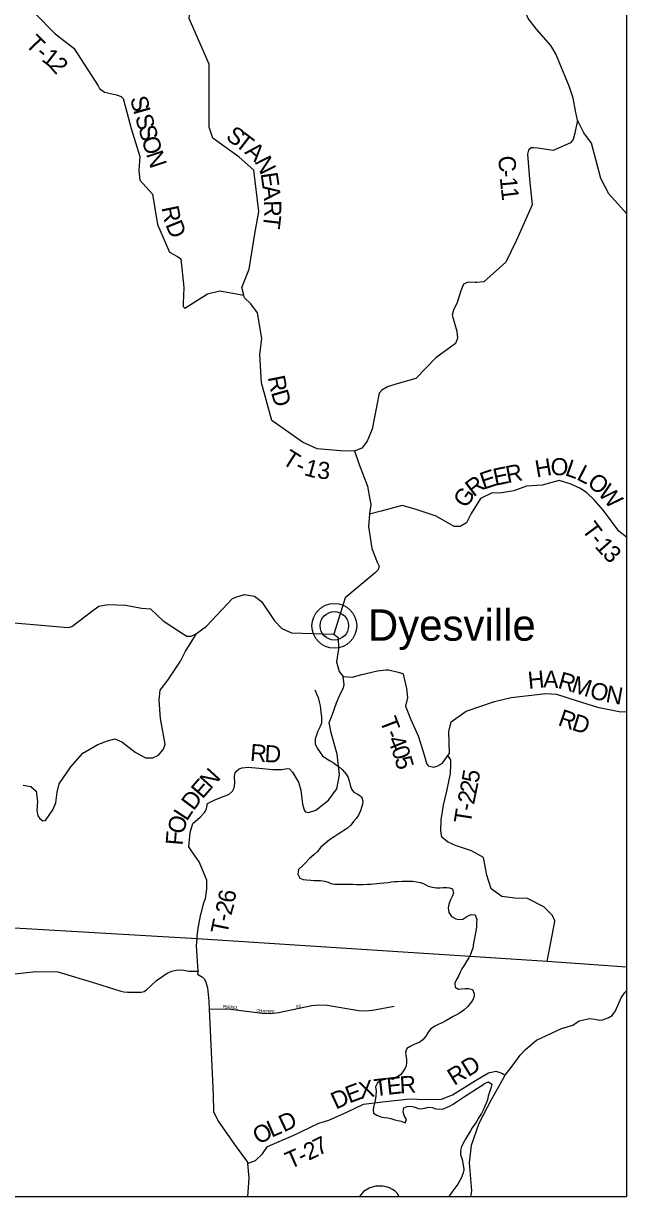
# Model space of a CAD drawing. Extents: x -15 to 405, y -40 to 87.
# Drawn here: x -10.265 to -8.262, y 14.129 to 18.029 of the extents above; entities that cross this region are included whole.
import ezdxf

# ---------------------------------------------------------------- set-up
doc = ezdxf.new("R2010")
doc.units = 0
for name, color, linetype in [('GM_P_State_Location', 7, 'Continuous'), ('GM_X_Major_Lake', 7, 'Continuous'), ('GM_X_Major_Lake_Text', 7, 'Continuous'), ('GM_X_Major_River', 7, 'Continuous'), ('GM_X_Minor_Lake', 7, 'Continuous'), ('GM_X_Minor_River', 7, 'Continuous'), ('GM_X_Rail_Line', 7, 'Continuous'), ('GM_X_Township', 7, 'Continuous'), ('GM_X_Township_Road', 7, 'Continuous'), ('GM_X_Township_ROW', 7, 'Continuous'), ('GM_X_Township_Subdivision_Text', 7, 'Continuous'), ('GM_X_Township_Text', 7, 'Continuous')]:
    doc.layers.add(name, color=color, linetype=linetype)

msp = doc.modelspace()

# ---------------------------------------------------------------- linework, layer by layer
at = {"layer": 'GM_P_State_Location'}
for points in [[(-9.1653, 16.608), (-9.1986, 16.6073), (-9.2895, 16.6146), (-9.338, 16.6373), (-9.4395, 16.7094), (-9.4747, 16.8339), (-9.4804, 16.9288), (-9.4733, 16.982), (-9.4872, 17.0673), (-9.5096, 17.0974), (-9.5307, 17.1173), (-9.5328, 17.1252), (-9.5398, 17.1513), (-9.5154, 17.2124), (-9.4962, 17.3291), (-9.4833, 17.4044), (-9.4997, 17.5413), (-9.5484, 17.5844), (-9.6358, 17.648), (-9.6476, 17.6847), (-9.6484, 17.8939), (-9.7143, 18.045), (-9.6672, 18.4388)], [(-10.228, 18.0646), (-10.1595, 17.9948), (-10.0974, 17.9473), (-10.017, 17.8221), (-10.0122, 17.8123), (-9.9955, 17.8007), (-9.9559, 17.7913), (-9.9406, 17.7857), (-9.9341, 17.7798), (-9.9265, 17.7503), (-9.9075, 17.6799), (-9.8787, 17.5864), (-9.882, 17.5397), (-9.8786, 17.5082), (-9.8367, 17.4616), (-9.82, 17.3608), (-9.7798, 17.269), (-9.7538, 17.2537), (-9.7427, 17.2466), (-9.7321, 17.1507), (-9.7346, 17.0975), (-9.7341, 17.088), (-9.7291, 17.0827), (-9.654, 17.1303), (-9.6123, 17.1406), (-9.5328, 17.1252)], [(-8.2623, 16.3215), (-8.2872, 16.3408), (-8.3101, 16.3711), (-8.3391, 16.4097), (-8.3693, 16.4448), (-8.3941, 16.4686), (-8.4153, 16.4832), (-8.4491, 16.4986), (-8.4858, 16.5099), (-8.5427, 16.4945), (-8.5943, 16.4908), (-8.6368, 16.475), (-8.6763, 16.468), (-8.7108, 16.4675), (-8.7476, 16.4495), (-8.7782, 16.3996), (-8.794, 16.3684), (-8.8141, 16.3569), (-8.8342, 16.3564), (-8.8947, 16.3914), (-8.9643, 16.4146), (-9.0069, 16.4262), (-9.0775, 16.4076), (-9.1152, 16.3978)], [(-10.2654, 15.4963), (-10.2403, 15.4918), (-10.2226, 15.4764), (-10.2184, 15.4426), (-10.2202, 15.4127), (-10.2166, 15.3941), (-10.2102, 15.3857), (-10.2004, 15.3776), (-10.1916, 15.379), (-10.1677, 15.4147), (-10.1576, 15.4381), (-10.153, 15.4733), (-10.1463, 15.5008), (-10.1073, 15.5572), (-10.0673, 15.6029), (-10.0183, 15.6319), (-9.9862, 15.644), (-9.9614, 15.6501), (-9.9379, 15.6403), (-9.8941, 15.6064), (-9.8601, 15.587), (-9.835, 15.587), (-9.8163, 15.5959), (-9.7995, 15.6159), (-9.7946, 15.6324), (-9.8097, 15.7186), (-9.8141, 15.779), (-9.8107, 15.8123), (-9.7852, 15.8453), (-9.7432, 15.9087), (-9.7265, 15.9421), (-9.7127, 15.9646), (-9.6902, 16.001)], [(-9.2345, 15.9985), (-9.2202, 15.9874), (-9.2191, 15.9499), (-9.2254, 15.9069), (-9.2163, 15.874), (-9.203, 15.8584), (-9.1737, 15.8555), (-9.1416, 15.864), (-9.0897, 15.8771), (-9.0618, 15.8797), (-9.0529, 15.88), (-9.025, 15.8731), (-9.0249, 15.8731)], [(-9.6727, 15.0793), (-9.6664, 15.107), (-9.6604, 15.12), (-9.656, 15.1509), (-9.6561, 15.1812), (-9.6817, 15.2415), (-9.7023, 15.2713), (-9.7154, 15.292), (-9.7115, 15.3397), (-9.7021, 15.3688), (-9.6783, 15.3905), (-9.6637, 15.4058), (-9.6579, 15.4151), (-9.6563, 15.4235), (-9.6539, 15.436), (-9.6317, 15.4471), (-9.6015, 15.4588), (-9.5832, 15.4654), (-9.5702, 15.4762), (-9.5651, 15.4876), (-9.5627, 15.5027), (-9.5636, 15.527), (-9.5617, 15.5378), (-9.5558, 15.5439), (-9.548, 15.5514), (-9.5386, 15.5539), (-9.5188, 15.556), (-9.4823, 15.5528), (-9.4371, 15.5492), (-9.4085, 15.5488), (-9.3883, 15.5516), (-9.3811, 15.5511), (-9.3717, 15.54), (-9.3515, 15.5064), (-9.3442, 15.4801), (-9.3385, 15.4338), (-9.3341, 15.4182), (-9.33, 15.4098), (-9.327, 15.4082), (-9.3179, 15.4062), (-9.2942, 15.4139), (-9.2521, 15.4463), (-9.2247, 15.4846), (-9.2151, 15.5308), (-9.2231, 15.5999), (-9.2426, 15.671), (-9.2499, 15.7052), (-9.2397, 15.729), (-9.2249, 15.7698), (-9.2135, 15.7996), (-9.2032, 15.8177), (-9.1999, 15.8307), (-9.203, 15.8584)], [(-9.0249, 15.8731), (-9.0055, 15.8683), (-9.0036, 15.8656), (-8.9926, 15.8183), (-8.9898, 15.7866), (-8.9962, 15.7597), (-8.9799, 15.7174), (-8.9546, 15.6605), (-8.9384, 15.6117), (-8.931, 15.5858), (-8.9273, 15.5732), (-8.924, 15.5648), (-8.9214, 15.561), (-8.9032, 15.5563), (-8.8914, 15.5596), (-8.8738, 15.5696), (-8.8553, 15.5954), (-8.8503, 15.6024), (-8.8523, 15.675), (-8.844, 15.7069), (-8.7942, 15.7421), (-8.7008, 15.7745), (-8.6456, 15.7876), (-8.53, 15.8009), (-8.4943, 15.7994), (-8.4299, 15.7778), (-8.3591, 15.7558), (-8.281, 15.7405), (-8.2623, 15.7418)], [(-8.8231, 15.2936), (-8.8279, 15.2952), (-8.857, 15.3077), (-8.8751, 15.3234), (-8.8791, 15.3448), (-8.8776, 15.3808), (-8.8699, 15.4301), (-8.8591, 15.4768), (-8.8472, 15.5355), (-8.8454, 15.5648), (-8.8452, 15.5811), (-8.8553, 15.5954)], [(-9.6876, 14.9939), (-9.6851, 15.0209), (-9.6754, 15.0676), (-9.6727, 15.0793)], [(-9.6847, 14.8784), (-9.69, 14.9625), (-9.6883, 14.9862), (-9.6876, 14.9939)], [(-9.5209, 14.2389), (-9.4945, 14.2483), (-9.4711, 14.2711), (-9.4541, 14.2952), (-9.3666, 14.3327), (-9.2841, 14.3733), (-9.2509, 14.3827), (-9.189, 14.41), (-9.1355, 14.4358), (-9.0726, 14.4441), (-8.9816, 14.4535), (-8.9318, 14.4514), (-8.8766, 14.4525), (-8.8396, 14.4672), (-8.7638, 14.5144), (-8.7201, 14.5407), (-8.6961, 14.5457), (-8.676, 14.5394), (-8.6654, 14.5321)], [(-9.018, 14.1289), (-9.0188, 14.1308), (-9.0243, 14.14), (-9.0308, 14.1471), (-9.0389, 14.1527), (-9.0496, 14.1573), (-9.0608, 14.1611), (-9.0719, 14.1636), (-9.084, 14.1637), (-9.0951, 14.1631), (-9.1141, 14.1581), (-9.1352, 14.1456), (-9.1492, 14.1289)]]:
    msp.add_lwpolyline(points, dxfattribs=at)
at = {"layer": 'GM_X_Major_Lake_Text'}
msp.add_lwpolyline([(-8.5259, 14.9104), (-8.5113, 14.9854), (-8.502, 15.0312), (-8.5, 15.0452), (-8.508, 15.0638), (-8.5373, 15.0916), (-8.5906, 15.1199), (-8.6335, 15.1211), (-8.6768, 15.1268), (-8.7119, 15.1523), (-8.7263, 15.1976), (-8.7371, 15.2559), (-8.7771, 15.2783), (-8.8101, 15.2893), (-8.8231, 15.2936)], dxfattribs=at)
at = {"layer": 'GM_X_Major_River'}
msp.add_lwpolyline([(-9.6478, 14.7518), (-9.5851, 14.7532), (-9.4727, 14.7387), (-9.4461, 14.7371), (-9.4182, 14.7404), (-9.3075, 14.7642), (-9.2841, 14.7667), (-9.2565, 14.7648), (-9.151, 14.7474), (-9.1299, 14.7465), (-9.1058, 14.7486), (-9.0342, 14.7615)], dxfattribs=at)
at = {"layer": 'GM_X_Rail_Line'}
for p, q in [((-9.6883, 14.9862), (-10.7339, 15.0461)), ((-8.5259, 14.9104), (-9.6883, 14.9862)), ((-8.2623, 14.8918), (-8.5259, 14.9104))]:
    msp.add_line(p, q, dxfattribs=at)
at = {"layer": 'GM_X_Township'}
for p in [(-8.2623, 20.9289), (-15.0623, 14.1289)]:
    msp.add_line(p, (-8.2623, 14.1289), dxfattribs=at)
at = {"layer": 'GM_X_Township_Road'}
for points in [[(-9.2973, 15.8139), (-9.2912, 15.8002), (-9.2866, 15.7877), (-9.2828, 15.7741), (-9.2797, 15.7609), (-9.2781, 15.7499), (-9.2773, 15.7385), (-9.2753, 15.7237), (-9.2753, 15.7138), (-9.2756, 15.7032), (-9.2805, 15.6896), (-9.288, 15.6736), (-9.2914, 15.6626), (-9.2962, 15.6504), (-9.2958, 15.6345), (-9.2893, 15.6193), (-9.2801, 15.6057), (-9.2721, 15.5944), (-9.2577, 15.5838), (-9.2463, 15.5774), (-9.2368, 15.5714), (-9.2265, 15.5643), (-9.2159, 15.5575), (-9.2064, 15.5488), (-9.1935, 15.5333), (-9.1866, 15.522), (-9.1835, 15.5114), (-9.1797, 15.4962), (-9.175, 15.483), (-9.1678, 15.4731), (-9.1545, 15.4664), (-9.1427, 15.4577), (-9.1374, 15.4448), (-9.1385, 15.4319), (-9.1418, 15.4224), (-9.1459, 15.411), (-9.1519, 15.3974), (-9.1602, 15.3859), (-9.1685, 15.3757), (-9.1776, 15.3631), (-9.1889, 15.3536), (-9.201, 15.3456), (-9.2108, 15.3394), (-9.2232, 15.331), (-9.2331, 15.3245), (-9.2482, 15.3146), (-9.2625, 15.3032), (-9.2768, 15.2902), (-9.29, 15.2754), (-9.3006, 15.2651), (-9.3146, 15.2525), (-9.3266, 15.2399), (-9.3383, 15.2285), (-9.3511, 15.2159), (-9.3537, 15.2007), (-9.3468, 15.1875), (-9.3358, 15.1826), (-9.3252, 15.1819), (-9.3101, 15.1805), (-9.2998, 15.1801), (-9.2877, 15.1798), (-9.2779, 15.1791), (-9.2654, 15.1776), (-9.2532, 15.1739), (-9.2437, 15.1701), (-9.2305, 15.1679), (-9.2172, 15.168), (-9.207, 15.1677), (-9.1968, 15.1677), (-9.1854, 15.1674), (-9.1714, 15.1674), (-9.16, 15.1667), (-9.1479, 15.1668), (-9.1365, 15.1665), (-9.1225, 15.1669), (-9.1127, 15.1677), (-9.1013, 15.1689), (-9.0911, 15.1701), (-9.0813, 15.1709), (-9.0684, 15.1717), (-9.054, 15.1733), (-9.043, 15.1749), (-9.0324, 15.176), (-9.0222, 15.1768), (-9.007, 15.1773), (-8.987, 15.1774), (-8.9722, 15.1771), (-8.9601, 15.1756), (-8.9472, 15.1734), (-8.9366, 15.17), (-8.9206, 15.161), (-8.9066, 15.1576), (-8.8933, 15.1554), (-8.8812, 15.1555), (-8.871, 15.1559), (-8.8592, 15.1567), (-8.8498, 15.1556), (-8.8399, 15.1519), (-8.8364, 15.1379), (-8.8409, 15.1269), (-8.8477, 15.1132)], [(-8.8477, 15.1132), (-8.8522, 15.0999), (-8.854, 15.0889), (-8.8524, 15.0737), (-8.8433, 15.0597), (-8.8285, 15.0522), (-8.8186, 15.05), (-8.8057, 15.0512), (-8.7925, 15.0596), (-8.7782, 15.0661), (-8.7649, 15.065), (-8.7595, 15.0502), (-8.7599, 15.0389), (-8.7609, 15.0263), (-8.762, 15.0169), (-8.7639, 15.0062), (-8.7657, 14.9933), (-8.7679, 14.9819), (-8.7702, 14.9709), (-8.7731, 14.9546), (-8.7765, 14.9432), (-8.7802, 14.9337), (-8.7855, 14.9227), (-8.7926, 14.9124), (-8.8005, 14.8995), (-8.8096, 14.8858), (-8.8152, 14.8729), (-8.8204, 14.8615), (-8.8268, 14.8504), (-8.8328, 14.8387), (-8.8316, 14.825), (-8.8206, 14.8186), (-8.8104, 14.819), (-8.7983, 14.8202), (-8.7865, 14.8207), (-8.774, 14.8173), (-8.7683, 14.8041), (-8.7686, 14.7938), (-8.7735, 14.7805), (-8.781, 14.7703), (-8.7893, 14.7604), (-8.8029, 14.7485), (-8.8165, 14.739), (-8.8271, 14.7325), (-8.8376, 14.7271), (-8.8486, 14.7206), (-8.8622, 14.7134), (-8.8739, 14.7069), (-8.886, 14.7015), (-8.8989, 14.695), (-8.9128, 14.6851), (-8.9207, 14.6752), (-8.9283, 14.6626), (-8.9381, 14.6501), (-8.9505, 14.6409), (-8.9656, 14.6355), (-8.9781, 14.6294), (-8.9921, 14.6206), (-8.9962, 14.6088), (-8.995, 14.5979), (-8.9931, 14.5861), (-8.993, 14.5744), (-8.9945, 14.5633), (-8.9982, 14.5531), (-9.0046, 14.5432), (-9.0133, 14.5333), (-9.0276, 14.5245), (-9.0382, 14.5184), (-9.0511, 14.5218), (-9.0636, 14.5194), (-9.0765, 14.5148), (-9.0889, 14.5068), (-9.0957, 14.4935), (-9.0941, 14.4791), (-9.0944, 14.4647), (-9.0959, 14.4548), (-9.0985, 14.4442), (-9.1015, 14.4309), (-9.1037, 14.4184), (-9.1025, 14.4058), (-9.0915, 14.3994), (-9.0782, 14.3942), (-9.0661, 14.392), (-9.0547, 14.3905), (-9.0445, 14.3887), (-9.032, 14.3838), (-9.0221, 14.3816), (-9.0103, 14.3797), (-8.9971, 14.3745), (-8.9933, 14.3855), (-9.001, 14.3987), (-9.004, 14.4108), (-9.0018, 14.4234), (-8.9901, 14.4287), (-8.9803, 14.4292), (-8.9678, 14.4277), (-8.9545, 14.4217), (-8.945, 14.4202), (-8.9321, 14.4226), (-8.9193, 14.4256), (-8.9071, 14.4246)], [(-8.9071, 14.4246), (-8.8954, 14.4201), (-8.8825, 14.419), (-8.87, 14.4209), (-8.8602, 14.4248), (-8.8504, 14.4298), (-8.8379, 14.4363), (-8.8269, 14.4439), (-8.813, 14.4527), (-8.8031, 14.4592), (-8.7793, 14.4752), (-8.7695, 14.4813), (-8.7567, 14.4893), (-8.7431, 14.4981), (-8.7333, 14.505), (-8.7208, 14.5104), (-8.709, 14.5025), (-8.7131, 14.4888), (-8.7169, 14.4762), (-8.7213, 14.463), (-8.7243, 14.4508), (-8.7277, 14.4413), (-8.7326, 14.4291), (-8.7378, 14.4162), (-8.7442, 14.4052), (-8.7525, 14.3915), (-8.7588, 14.3797), (-8.766, 14.3695), (-8.775, 14.3569), (-8.7807, 14.347), (-8.7893, 14.3333), (-8.7957, 14.3215), (-8.8013, 14.312), (-8.81, 14.2957), (-8.8137, 14.2824), (-8.8137, 14.2672), (-8.8083, 14.2536), (-8.8056, 14.2384), (-8.8036, 14.2274), (-8.8028, 14.218), (-8.8043, 14.2073), (-8.8099, 14.1925), (-8.8155, 14.1826), (-8.8223, 14.1701), (-8.8325, 14.1572), (-8.8419, 14.1438), (-8.8521, 14.129), (-8.8521, 14.1289)]]:
    msp.add_lwpolyline(points, dxfattribs=at)
at = {"layer": 'GM_X_Township_Subdivision_Text'}
for radius in [0.0744, 0.0472]:
    msp.add_circle((-9.2325, 16.0263), radius, dxfattribs=at)
at = {"layer": 'GM_X_Township_Text'}
for points in [[(-8.4252, 17.7077), (-8.4311, 17.7384), (-8.4392, 17.7805), (-8.4527, 17.8206), (-8.4846, 17.8979), (-8.4965, 17.9278), (-8.5137, 17.9558), (-8.5614, 18.0103), (-8.5889, 18.0451), (-8.6085, 18.0932), (-8.636, 18.1371), (-8.6738, 18.193), (-8.7329, 18.2489), (-8.7912, 18.2783), (-8.8098, 18.2839), (-8.8228, 18.2922), (-8.8169, 18.343), (-8.7836, 18.3792), (-8.7622, 18.4128)], [(-8.4252, 17.7077), (-8.4338, 17.6647), (-8.439, 17.6427), (-8.4485, 17.6317), (-8.5061, 17.6071), (-8.5563, 17.6141), (-8.5711, 17.6159), (-8.5791, 17.6155), (-8.5874, 17.6082), (-8.5907, 17.5949), (-8.5839, 17.5111), (-8.5752, 17.4265), (-8.6275, 17.3082), (-8.6629, 17.2355), (-8.7363, 17.1699), (-8.7589, 17.168), (-8.7591, 17.168)], [(-8.2623, 17.397), (-8.3205, 17.4626), (-8.3473, 17.5141), (-8.3786, 17.6305), (-8.4038, 17.6656), (-8.4252, 17.7077)], [(-8.7591, 17.168), (-8.7648, 17.1675), (-8.7879, 17.1689), (-8.8031, 17.1624), (-8.8121, 17.1399), (-8.8241, 17.1011), (-8.8373, 17.0753), (-8.841, 17.0589), (-8.826, 17.0059), (-8.8232, 16.9824), (-8.8296, 16.9645), (-8.8959, 16.9179), (-8.962, 16.8488), (-9.0284, 16.8299), (-9.0557, 16.8211), (-9.0743, 16.81), (-9.0837, 16.8001), (-9.1068, 16.68), (-9.1237, 16.6405), (-9.1407, 16.6165), (-9.1615, 16.6095), (-9.1653, 16.608), (-9.1503, 16.5625), (-9.1222, 16.4903), (-9.1145, 16.4469), (-9.1115, 16.4309), (-9.1115, 16.4304)], [(-9.1115, 16.4304), (-9.1112, 16.429), (-9.1143, 16.4075), (-9.1152, 16.3978), (-9.1187, 16.3566), (-9.1077, 16.2834), (-9.0901, 16.2379), (-9.0841, 16.2251), (-9.0866, 16.2137), (-9.088, 16.211), (-9.0964, 16.2022), (-9.197, 16.1197), (-9.2345, 15.9985)], [(-10.3735, 16.0426), (-10.1161, 16.0205), (-10.104, 16.0239), (-10.0298, 16.0805), (-10.0141, 16.0918), (-9.9851, 16.0977), (-9.9254, 16.0946), (-9.873, 16.085), (-9.8429, 16.0825), (-9.801, 16.0428), (-9.7438, 16.0048), (-9.7218, 15.9916), (-9.7081, 15.9917), (-9.6956, 15.997), (-9.6902, 16.001), (-9.6566, 16.0257), (-9.5711, 16.117), (-9.556, 16.1222), (-9.5309, 16.1303), (-9.4977, 16.1246), (-9.4739, 16.1067), (-9.4307, 16.0435), (-9.407, 16.017), (-9.375, 16.0035), (-9.2345, 15.9985)], [(-10.3036, 14.8682), (-10.2236, 14.877), (-10.1502, 14.876), (-10.0254, 14.8388), (-9.9417, 14.8113), (-9.9312, 14.8092), (-9.9195, 14.8084), (-9.8741, 14.8084), (-9.8643, 14.8106), (-9.8567, 14.8157), (-9.8233, 14.8467), (-9.7873, 14.8713), (-9.7725, 14.8777), (-9.7581, 14.8814), (-9.7446, 14.8824), (-9.7334, 14.8819), (-9.7148, 14.878), (-9.6847, 14.8784), (-9.6872, 14.8679), (-9.6708, 14.8586), (-9.6642, 14.8523), (-9.6598, 14.8447), (-9.6541, 14.8227), (-9.649, 14.7785), (-9.6478, 14.7518), (-9.6425, 14.6332), (-9.6346, 14.4674), (-9.6333, 14.4113), (-9.6184, 14.38), (-9.558, 14.2942), (-9.5212, 14.2433), (-9.5209, 14.2389), (-9.5168, 14.1898), (-9.521, 14.1289)], [(-8.7787, 14.1289), (-8.7757, 14.1476), (-8.7831, 14.2411), (-8.7768, 14.3), (-8.7518, 14.373), (-8.7111, 14.452), (-8.6864, 14.4947), (-8.6654, 14.5321), (-8.6424, 14.5619), (-8.6151, 14.5984), (-8.5974, 14.6176), (-8.5607, 14.6492), (-8.4779, 14.6871), (-8.4409, 14.6992), (-8.4191, 14.713), (-8.3844, 14.721), (-8.3678, 14.7182), (-8.3503, 14.7157), (-8.3416, 14.7164), (-8.3236, 14.7231), (-8.3095, 14.7313), (-8.2991, 14.7468), (-8.2804, 14.7891), (-8.2681, 14.8076), (-8.2623, 14.8123)]]:
    msp.add_lwpolyline(points, dxfattribs=at)

# ---------------------------------------------------------------- texts
at = {"layer": 'GM_X_Major_Lake'}
for s, rotation, p in [('P', 359.4536, (-9.6032, 14.7553)), ('E', 359.4536, (-9.5965, 14.7552)), ('A', 357.3984, (-9.59, 14.7552)), ('R', 353.5498, (-9.5818, 14.7548)), ('S', 352.7123, (-9.5744, 14.754)), ('O', 352.6798, (-9.5678, 14.7531)), ('L', 352.7052, (-9.5595, 14.7521)), ('C', 350.9529, (-9.4921, 14.7436)), ('E', 350.9464, (-9.4846, 14.7424)), ('M', 352.9089, (-9.4777, 14.7413)), ('E', 356.3543, (-9.4672, 14.74)), ('T', 357.2393, (-9.4604, 14.7396)), ('E', 357.2399, (-9.4537, 14.7393)), ('R', 4.5431, (-9.4457, 14.739)), ('Y', 6.9604, (-9.4378, 14.7396)), ('RD', 11.895, (-9.3594, 14.7552))]:
    msp.add_text(s, height=0.00947, rotation=rotation, dxfattribs=at).set_placement(p)
at = {"layer": 'GM_X_Minor_Lake'}
for s, rotation, p in [('C', 274.0703, (-8.6883, 17.5875)), ('1', 275.3985, (-8.683, 17.5163)), ('-', 274.5449, (-8.685, 17.5405)), ('1', 276.6101, (-8.6796, 17.4802))]:
    msp.add_text(s, height=0.0568, rotation=rotation, dxfattribs=at).set_placement(p)
at = {"layer": 'GM_X_Minor_River'}
for s, height, rotation, p in [('T', 0.0568, 314.9788, (-10.2612, 17.9572)), ('-', 0.0568, 319.597, (-10.2275, 17.9237)), ('1', 0.0568, 322.2326, (-10.2075, 17.9068)), ('2', 0.0568, 311.1996, (-10.1819, 17.8874)), ('S', 0.0568, 284.1354, (-9.9111, 17.7805)), ('I', 0.0568, 285.7953, (-9.9013, 17.7416)), ('S', 0.0568, 286.1126, (-9.8949, 17.7188)), ('S', 0.0568, 286.1492, (-9.8842, 17.682)), ('S', 0.0568, 323.457, (-9.5962, 17.6469)), ('T', 0.0568, 322.2833, (-9.5656, 17.6242)), ('O', 0.0568, 286.6193, (-9.8734, 17.6447)), ('N', 0.0568, 288.3663, (-9.8585, 17.5949)), ('A', 0.0568, 318.6859, (-9.5327, 17.5988)), ('N', 0.0568, 296.6628, (-9.4987, 17.5704)), ('E', 0.0568, 278.2307, (-9.4777, 17.5303)), ('A', 0.0568, 276.6926, (-9.4716, 17.4886)), ('R', 0.0568, 271.2178, (-9.4659, 17.4404)), ('R', 0.0568, 281.4492, (-9.8067, 17.4171)), ('D', 0.0568, 291.9528, (-9.7942, 17.3607)), ('T', 0.0568, 263.2689, (-9.4648, 17.3958)), ('R', 0.0568, 281.4492, (-9.4538, 16.8529)), ('D', 0.0568, 286.2019, (-9.4433, 16.8023)), ('T', 0.0568, 327.633, (-9.4095, 16.5677)), ('1', 0.0568, 344.4218, (-9.3358, 16.528)), ('H', 0.0568, 9.5851, (-8.5611, 16.5191)), ('O', 0.0568, 359.6794, (-8.5144, 16.5272)), ('L', 0.0568, 340.5269, (-8.4694, 16.5278)), ('-', 0.0568, 335.7427, (-9.3659, 16.5408)), ('3', 0.0568, 355.1817, (-9.2907, 16.5166)), ('E', 0.0568, 18.477, (-8.7375, 16.4787)), ('E', 0.0568, 11.7478, (-8.6989, 16.4917)), ('R', 0.0568, 11.1783, (-8.6575, 16.5003)), ('L', 0.0568, 332.8044, (-8.4311, 16.5144)), ('R', 0.0568, 37.2016, (-8.7704, 16.4528)), ('O', 0.0568, 319.7243, (-8.3962, 16.4969)), ('W', 0.0568, 310.4939, (-8.3598, 16.4663)), ('G', 0.0568, 56.7898, (-8.7943, 16.4147)), ('T', 0.0568, 306.5296, (-8.4132, 16.3459)), ('-', 0.0568, 308.3582, (-8.3867, 16.3102)), ('1', 0.0568, 311.4269, (-8.37, 16.2894)), ('3', 0.0568, 314.8505, (-8.3444, 16.2604)), ('H', 0.0568, 5.5127, (-8.5873, 15.8168)), ('A', 0.0568, 357.8467, (-8.5395, 15.8215)), ('R', 0.0568, 344.1886, (-8.4931, 15.8202)), ('M', 0.0568, 342.2254, (-8.4487, 15.8077)), ('O', 0.0568, 344.1537, (-8.3879, 15.7882)), ('N', 0.0568, 349.8985, (-8.3338, 15.7732)), ('T', 0.0568, 290.9674, (-9.0824, 15.7113)), ('R', 0.0568, 341.1824, (-8.4928, 15.6967)), ('D', 0.0568, 342.9862, (-8.4468, 15.681)), ('-', 0.0568, 293.4297, (-9.0662, 15.6692)), ('4', 0.0568, 292.244, (-9.0571, 15.6481)), ('R', 0.0568, 355.2017, (-9.5138, 15.5777)), ('D', 0.0568, 357.1009, (-9.4653, 15.5737)), ('0', 0.0568, 288.8315, (-9.0441, 15.6165)), ('5', 0.0568, 286.142, (-9.033, 15.5841)), ('N', 0.0568, 47.6592, (-9.643, 15.4803)), ('5', 0.0568, 81.217, (-8.7538, 15.5021)), ('E', 0.0568, 49.0854, (-9.6705, 15.4485)), ('2', 0.0568, 78.0808, (-8.7617, 15.4645)), ('D', 0.0568, 53.149, (-9.6999, 15.4093)), ('2', 0.0568, 78.0808, (-8.7689, 15.4303)), ('L', 0.0568, 56.7307, (-9.7226, 15.3745)), ('T', 0.0568, 80.8456, (-8.7799, 15.3661)), ('-', 0.0568, 79.2197, (-8.7732, 15.4077)), ('O', 0.0568, 74.8522, (-9.7338, 15.3306)), ('F', 0.0568, 85.2766, (-9.7364, 15.295)), ('6', 0.0568, 81.3159, (-9.5636, 15.1029)), ('2', 0.0568, 73.853, (-9.5751, 15.0615)), ('-', 0.0568, 77.9445, (-9.5797, 15.0397)), ('T', 0.0568, 78.3833, (-9.5882, 14.9982)), ('RD', 0.05682, 31.799, (-8.8346, 14.4962)), ('X', 0.0568, 11.5192, (-9.1455, 14.4523)), ('T', 0.0568, 6.5972, (-9.0978, 14.4621)), ('E', 0.0568, 6.317, (-9.0556, 14.4669)), ('R', 0.0568, 3.5108, (-9.0141, 14.4715)), ('D', 0.0568, 24.8347, (-9.2273, 14.4174)), ('E', 0.0568, 20.5957, (-9.183, 14.438)), ('D', 0.0568, 24.9835, (-9.4006, 14.3418)), ('O', 0.0568, 30.1678, (-9.4829, 14.2999)), ('L', 0.0568, 23.2802, (-9.4413, 14.3242)), ('7', 0.0568, 26.5174, (-9.2855, 14.2631)), ('T', 0.0568, 23.4816, (-9.3801, 14.2197)), ('2', 0.0568, 25.8495, (-9.3176, 14.2475)), ('-', 0.0568, 24.9089, (-9.3397, 14.2372))]:
    msp.add_text(s, height=height, rotation=rotation, dxfattribs=at).set_placement(p)
at = {"layer": 'GM_X_Township_ROW'}
msp.add_text('Dyesville', height=0.10417, rotation=0, dxfattribs=at).set_placement((-9.121, 15.9769))

doc.saveas('drawing.dxf')
